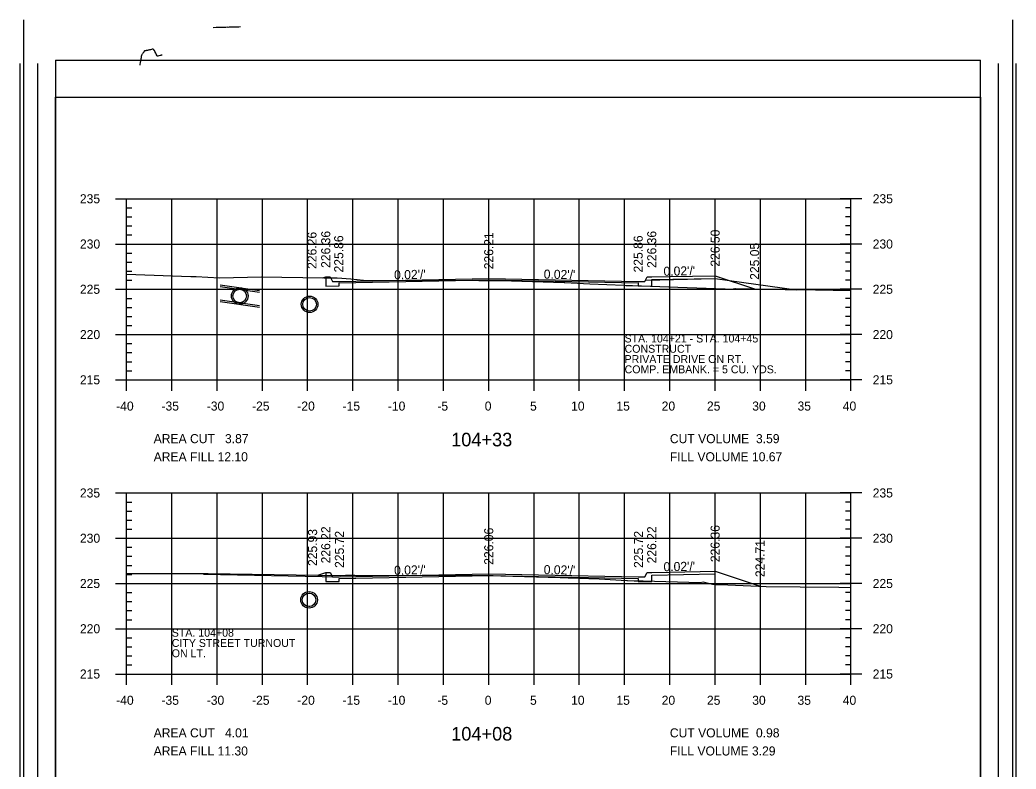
# Model space of a CAD drawing. Extents: x 1367903 to 1373764, y 376865 to 382130.
# Drawn here: x 1370689.3 to 1370909.3, y 377454.8 to 377620.4 of the extents above; entities that cross this region are included whole.
import ezdxf

# ---------------------------------------------------------------- set-up
doc = ezdxf.new("R2010")
doc.units = 0
for name, color, linetype in [('R_Axis', 7, 'Continuous'), ('R_Axis Annot', 7, 'Continuous'), ('R_Border', 7, 'Continuous'), ('R_Border PE', 7, 'Continuous'), ('R_Draft', 7, 'Continuous'), ('R_Drive', 7, 'Continuous'), ('R_Exist Surface', 7, 'Continuous'), ('R_Fin Surface', 7, 'Continuous'), ('R_Fin Surface Annot', 7, 'Continuous'), ('R_Grid', 7, 'Continuous'), ('R_Water', 7, 'Continuous')]:
    doc.layers.add(name, color=color, linetype=linetype)

msp = doc.modelspace()

# ---------------------------------------------------------------- linework, layer by layer
for points in [[(1370756.87, 377563.56), (1370756.87, 377562.89), (1370756.87, 377562.89), (1370756.87, 377561.53), (1370759.87, 377561.59), (1370759.87, 377562.25), (1370792.87, 377562.91), (1370825.87, 377562.25), (1370825.87, 377561.59), (1370828.87, 377561.53), (1370828.87, 377562.97), (1370842.87, 377563.25), (1370842.87, 377563.84)], [(1370756.87, 377498.28), (1370756.87, 377497.61), (1370756.87, 377497.61), (1370756.87, 377496.25), (1370759.87, 377496.31), (1370759.87, 377496.97), (1370792.87, 377497.63), (1370825.87, 377496.97), (1370825.87, 377496.31), (1370828.87, 377496.25), (1370828.87, 377497.69), (1370842.87, 377497.97), (1370842.87, 377498.56)]]:
    msp.add_lwpolyline(points)
at = {"layer": 'R_Axis'}
for p, q in [((1370710.47, 377580.84), (1370715.27, 377580.84)), ((1370712.87, 377540.84), (1370712.87, 377580.84)), ((1370875.27, 377580.84), (1370870.47, 377580.84)), ((1370872.87, 377540.84), (1370872.87, 377580.84)), ((1370712.87, 377578.84), (1370714.07, 377578.84)), ((1370872.87, 377578.84), (1370871.67, 377578.84)), ((1370712.87, 377576.84), (1370714.07, 377576.84)), ((1370872.87, 377576.84), (1370871.67, 377576.84)), ((1370712.87, 377574.84), (1370714.07, 377574.84)), ((1370872.87, 377574.84), (1370871.67, 377574.84)), ((1370712.87, 377572.84), (1370714.07, 377572.84)), ((1370872.87, 377572.84), (1370871.67, 377572.84)), ((1370710.47, 377570.84), (1370715.27, 377570.84)), ((1370875.27, 377570.84), (1370870.47, 377570.84)), ((1370712.87, 377568.84), (1370714.07, 377568.84)), ((1370712.87, 377566.84), (1370714.07, 377566.84)), ((1370872.87, 377568.84), (1370871.67, 377568.84)), ((1370872.87, 377566.84), (1370871.67, 377566.84)), ((1370712.87, 377564.84), (1370714.07, 377564.84)), ((1370872.87, 377564.84), (1370871.67, 377564.84)), ((1370712.87, 377562.84), (1370714.07, 377562.84)), ((1370872.87, 377562.84), (1370871.67, 377562.84)), ((1370710.47, 377560.84), (1370715.27, 377560.84)), ((1370875.27, 377560.84), (1370870.47, 377560.84)), ((1370712.87, 377558.84), (1370714.07, 377558.84)), ((1370872.87, 377558.84), (1370871.67, 377558.84)), ((1370712.87, 377556.84), (1370714.07, 377556.84)), ((1370872.87, 377556.84), (1370871.67, 377556.84)), ((1370712.87, 377554.84), (1370714.07, 377554.84)), ((1370872.87, 377554.84), (1370871.67, 377554.84)), ((1370712.87, 377552.84), (1370714.07, 377552.84)), ((1370872.87, 377552.84), (1370871.67, 377552.84)), ((1370710.47, 377550.84), (1370715.27, 377550.84)), ((1370875.27, 377550.84), (1370870.47, 377550.84)), ((1370712.87, 377548.84), (1370714.07, 377548.84)), ((1370872.87, 377548.84), (1370871.67, 377548.84)), ((1370712.87, 377546.84), (1370714.07, 377546.84)), ((1370712.87, 377544.84), (1370714.07, 377544.84)), ((1370872.87, 377546.84), (1370871.67, 377546.84)), ((1370872.87, 377544.84), (1370871.67, 377544.84)), ((1370712.87, 377538.44), (1370712.87, 377543.24)), ((1370712.87, 377542.84), (1370714.07, 377542.84)), ((1370722.87, 377538.44), (1370722.87, 377543.24)), ((1370732.87, 377538.44), (1370732.87, 377543.24)), ((1370742.87, 377538.44), (1370742.87, 377543.24)), ((1370752.87, 377538.44), (1370752.87, 377543.24)), ((1370762.87, 377538.44), (1370762.87, 377543.24)), ((1370772.87, 377538.44), (1370772.87, 377543.24)), ((1370782.87, 377538.44), (1370782.87, 377543.24)), ((1370792.87, 377538.44), (1370792.87, 377543.24)), ((1370802.87, 377538.44), (1370802.87, 377543.24)), ((1370812.87, 377538.44), (1370812.87, 377543.24)), ((1370822.87, 377538.44), (1370822.87, 377543.24)), ((1370832.87, 377538.44), (1370832.87, 377543.24)), ((1370842.87, 377538.44), (1370842.87, 377543.24)), ((1370852.87, 377538.44), (1370852.87, 377543.24)), ((1370862.87, 377538.44), (1370862.87, 377543.24)), ((1370872.87, 377542.84), (1370871.67, 377542.84)), ((1370872.87, 377538.44), (1370872.87, 377543.24)), ((1370710.47, 377540.84), (1370715.27, 377540.84)), ((1370712.87, 377540.84), (1370872.87, 377540.84)), ((1370875.27, 377540.84), (1370870.47, 377540.84)), ((1370710.47, 377515.84), (1370715.27, 377515.84)), ((1370712.87, 377475.84), (1370712.87, 377515.84)), ((1370875.27, 377515.84), (1370870.47, 377515.84)), ((1370872.87, 377475.84), (1370872.87, 377515.84)), ((1370712.87, 377513.84), (1370714.07, 377513.84)), ((1370712.87, 377511.84), (1370714.07, 377511.84)), ((1370872.87, 377513.84), (1370871.67, 377513.84)), ((1370872.87, 377511.84), (1370871.67, 377511.84)), ((1370712.87, 377509.84), (1370714.07, 377509.84)), ((1370872.87, 377509.84), (1370871.67, 377509.84)), ((1370712.87, 377507.84), (1370714.07, 377507.84)), ((1370872.87, 377507.84), (1370871.67, 377507.84)), ((1370710.47, 377505.84), (1370715.27, 377505.84)), ((1370875.27, 377505.84), (1370870.47, 377505.84)), ((1370712.87, 377503.84), (1370714.07, 377503.84)), ((1370872.87, 377503.84), (1370871.67, 377503.84)), ((1370712.87, 377501.84), (1370714.07, 377501.84)), ((1370872.87, 377501.84), (1370871.67, 377501.84)), ((1370712.87, 377499.84), (1370714.07, 377499.84)), ((1370872.87, 377499.84), (1370871.67, 377499.84)), ((1370712.87, 377497.84), (1370714.07, 377497.84)), ((1370872.87, 377497.84), (1370871.67, 377497.84)), ((1370710.47, 377495.84), (1370715.27, 377495.84)), ((1370875.27, 377495.84), (1370870.47, 377495.84)), ((1370712.87, 377493.84), (1370714.07, 377493.84)), ((1370872.87, 377493.84), (1370871.67, 377493.84)), ((1370712.87, 377491.84), (1370714.07, 377491.84)), ((1370712.87, 377489.84), (1370714.07, 377489.84)), ((1370872.87, 377491.84), (1370871.67, 377491.84)), ((1370872.87, 377489.84), (1370871.67, 377489.84)), ((1370712.87, 377487.84), (1370714.07, 377487.84)), ((1370872.87, 377487.84), (1370871.67, 377487.84)), ((1370710.47, 377485.84), (1370715.27, 377485.84)), ((1370875.27, 377485.84), (1370870.47, 377485.84)), ((1370712.87, 377483.84), (1370714.07, 377483.84)), ((1370872.87, 377483.84), (1370871.67, 377483.84)), ((1370712.87, 377481.84), (1370714.07, 377481.84)), ((1370872.87, 377481.84), (1370871.67, 377481.84)), ((1370712.87, 377479.84), (1370714.07, 377479.84)), ((1370872.87, 377479.84), (1370871.67, 377479.84)), ((1370712.87, 377473.44), (1370712.87, 377478.24)), ((1370712.87, 377477.84), (1370714.07, 377477.84)), ((1370722.87, 377473.44), (1370722.87, 377478.24)), ((1370732.87, 377473.44), (1370732.87, 377478.24)), ((1370742.87, 377473.44), (1370742.87, 377478.24)), ((1370752.87, 377473.44), (1370752.87, 377478.24)), ((1370762.87, 377473.44), (1370762.87, 377478.24)), ((1370772.87, 377473.44), (1370772.87, 377478.24)), ((1370782.87, 377473.44), (1370782.87, 377478.24)), ((1370792.87, 377473.44), (1370792.87, 377478.24)), ((1370802.87, 377473.44), (1370802.87, 377478.24)), ((1370812.87, 377473.44), (1370812.87, 377478.24)), ((1370822.87, 377473.44), (1370822.87, 377478.24)), ((1370832.87, 377473.44), (1370832.87, 377478.24)), ((1370842.87, 377473.44), (1370842.87, 377478.24)), ((1370852.87, 377473.44), (1370852.87, 377478.24)), ((1370862.87, 377473.44), (1370862.87, 377478.24)), ((1370872.87, 377477.84), (1370871.67, 377477.84)), ((1370872.87, 377473.44), (1370872.87, 377478.24)), ((1370710.47, 377475.84), (1370715.27, 377475.84)), ((1370712.87, 377475.84), (1370872.87, 377475.84)), ((1370875.27, 377475.84), (1370870.47, 377475.84))]:
    msp.add_line(p, q, dxfattribs=at)
at = {"layer": 'R_Border'}
for p, q in [((1370690.14, 377620.35), (1370690.14, 377279.12)), ((1370908.53, 377620.35), (1370908.53, 377279.12)), ((1370697.17, 377611.47), (1370901.49, 377611.47)), ((1370697.17, 377611.47), (1370697.17, 377280.59)), ((1370901.49, 377280.59), (1370901.49, 377611.47))]:
    msp.add_line(p, q, dxfattribs=at)
at = {"layer": 'R_Border PE'}
for p, q in [((1370689.33, 377610.76), (1370689.33, 377288.8)), ((1370693.25, 377610.76), (1370693.25, 377288.8)), ((1370905.42, 377288.8), (1370905.42, 377610.76)), ((1370909.33, 377288.8), (1370909.33, 377610.76)), ((1370697.17, 377603.25), (1370901.49, 377603.25)), ((1370697.17, 377288.8), (1370697.17, 377603.25)), ((1370901.49, 377603.25), (1370901.49, 377288.8))]:
    msp.add_line(p, q, dxfattribs=at)
for points in [[(1370734.03, 377618.69), (1370733.97, 377618.69), (1370733.7, 377618.68), (1370733.57, 377618.68), (1370733.49, 377618.67), (1370733.34, 377618.67), (1370732.98, 377618.66), (1370732.65, 377618.65), (1370732.02, 377618.63)], [(1370734.48, 377618.7), (1370734.03, 377618.69)], [(1370738.04, 377618.79), (1370737.69, 377618.78), (1370737.5, 377618.78), (1370737.34, 377618.77), (1370737.11, 377618.76), (1370736.95, 377618.76), (1370736.76, 377618.75), (1370736.51, 377618.75), (1370736.32, 377618.74), (1370736.03, 377618.73), (1370735.94, 377618.73), (1370735.88, 377618.73), (1370735.67, 377618.72), (1370735.56, 377618.72), (1370735.34, 377618.71), (1370735.26, 377618.72), (1370734.84, 377618.7), (1370734.59, 377618.7), (1370734.48, 377618.7)], [(1370720.72, 377612.54), (1370720.71, 377612.55), (1370720.69, 377612.55), (1370720.66, 377612.55), (1370720.64, 377612.55), (1370720.62, 377612.55), (1370720.59, 377612.55), (1370720.56, 377612.55), (1370720.43, 377612.51), (1370720.31, 377612.48), (1370720.04, 377612.41), (1370719.82, 377612.36), (1370719.8, 377612.35), (1370719.77, 377612.35), (1370719.75, 377612.34), (1370719.74, 377612.34), (1370719.73, 377612.35), (1370719.71, 377612.35), (1370719.68, 377612.36), (1370719.66, 377612.38), (1370719.64, 377612.39), (1370719.62, 377612.4), (1370719.6, 377612.42), (1370719.59, 377612.45), (1370719.57, 377612.47), (1370719.56, 377612.5), (1370719.54, 377612.55), (1370719.44, 377612.76), (1370719.33, 377613), (1370719.23, 377613.23), (1370719.21, 377613.26), (1370719.2, 377613.28), (1370719.17, 377613.34), (1370719.13, 377613.39), (1370719.02, 377613.57), (1370718.94, 377613.69), (1370718.91, 377613.74), (1370718.89, 377613.76), (1370718.87, 377613.78), (1370718.85, 377613.81), (1370718.83, 377613.83), (1370718.82, 377613.84), (1370718.8, 377613.85), (1370718.78, 377613.87), (1370718.77, 377613.87), (1370718.73, 377613.88), (1370718.71, 377613.88), (1370718.69, 377613.88), (1370718.66, 377613.88), (1370718.55, 377613.86), (1370718.38, 377613.82), (1370718.18, 377613.77), (1370718.04, 377613.74), (1370717.94, 377613.72), (1370717.8, 377613.69), (1370717.68, 377613.66), (1370717.5, 377613.63), (1370717.28, 377613.58), (1370717.23, 377613.57), (1370717.11, 377613.54), (1370716.99, 377613.52), (1370716.95, 377613.51), (1370716.93, 377613.5), (1370716.9, 377613.5), (1370716.89, 377613.49), (1370716.88, 377613.49), (1370716.86, 377613.47), (1370716.83, 377613.46), (1370716.82, 377613.44), (1370716.79, 377613.42), (1370716.76, 377613.39), (1370716.73, 377613.35), (1370716.71, 377613.31), (1370716.67, 377613.26), (1370716.6, 377613.16), (1370716.51, 377613.02), (1370716.43, 377612.89), (1370716.33, 377612.75), (1370716.29, 377612.67), (1370716.25, 377612.62), (1370716.21, 377612.55), (1370716.2, 377612.54), (1370716.19, 377612.52), (1370716.18, 377612.5), (1370716.18, 377612.48), (1370716.17, 377612.46), (1370716.16, 377612.44), (1370716.16, 377612.42), (1370716.15, 377612.39), (1370716.14, 377612.37), (1370716.14, 377612.35), (1370716.14, 377612.33), (1370716.12, 377612.24), (1370716.08, 377612), (1370716.04, 377611.76), (1370716.02, 377611.65), (1370715.93, 377611.18), (1370715.9, 377611.04), (1370715.87, 377610.84), (1370715.81, 377610.54), (1370715.78, 377610.39)]]:
    msp.add_lwpolyline(points, dxfattribs=at)
at = {"layer": 'R_Drive'}
for p, q in [((1370827.53, 377562.89), (1370842.86, 377563.19)), ((1370842.86, 377563.19), (1370860.87, 377560.75)), ((1370729.87, 377497.9), (1370712.87, 377497.99)), ((1370729.87, 377497.9), (1370759.87, 377497.31))]:
    msp.add_line(p, q, dxfattribs=at)
at = {"layer": 'R_Exist Surface'}
for points in [[(1370712.87, 377564.2), (1370727.11, 377563.68), (1370728.26, 377563.65), (1370733.43, 377563.35), (1370742.68, 377563.56), (1370747.14, 377563.51), (1370756.46, 377563.35), (1370759.41, 377563.38), (1370762.41, 377563.17), (1370765.18, 377562.85), (1370790.66, 377562.81), (1370793.77, 377562.8), (1370795.54, 377562.75), (1370809.5, 377562.35), (1370809.71, 377562.35), (1370811.04, 377562.29), (1370815.18, 377562.08), (1370822.72, 377561.74), (1370823.18, 377561.7), (1370824.59, 377561.71), (1370834.64, 377561.33), (1370845.05, 377560.91), (1370846.42, 377560.87), (1370847.23, 377561.01), (1370847.37, 377561.02), (1370858.36, 377560.78), (1370865.02, 377560.69), (1370872.87, 377560.55)], [(1370712.87, 377498.02), (1370730.79, 377498.06), (1370730.86, 377498.06), (1370730.9, 377498.06), (1370760.03, 377497.63), (1370761.21, 377497.65), (1370763.2, 377497.7), (1370763.29, 377497.71), (1370791.93, 377497.6), (1370793.86, 377497.59), (1370795.54, 377497.55), (1370800.8, 377497.4), (1370808.63, 377497.19), (1370810.4, 377497.12), (1370817.29, 377496.9), (1370823.4, 377496.5), (1370823.54, 377496.5), (1370825.02, 377496.45), (1370826.99, 377496.4), (1370839.55, 377496.04), (1370840.2, 377496.24), (1370842.26, 377495.7), (1370842.86, 377495.65), (1370845.69, 377495.51), (1370852.44, 377495.27), (1370854.14, 377495.2), (1370861.63, 377495.08), (1370870.19, 377495), (1370872.87, 377494.98)]]:
    msp.add_lwpolyline(points, dxfattribs=at)
at = {"layer": 'R_Fin Surface'}
for points in [[(1370756.24, 377563.35), (1370756.87, 377563.56), (1370757.87, 377563.56), (1370758.37, 377562.56), (1370759.87, 377562.59), (1370781.87, 377563.03), (1370792.87, 377563.25), (1370803.87, 377563.03), (1370825.87, 377562.59), (1370827.37, 377562.56), (1370827.87, 377563.56), (1370828.87, 377563.56), (1370832.87, 377563.64), (1370842.87, 377563.84), (1370851.59, 377560.93)], [(1370755.15, 377497.7), (1370756.87, 377498.28), (1370757.87, 377498.28), (1370758.37, 377497.28), (1370759.87, 377497.31), (1370781.87, 377497.75), (1370792.87, 377497.97), (1370803.87, 377497.75), (1370825.87, 377497.31), (1370827.37, 377497.28), (1370827.87, 377498.28), (1370828.87, 377498.28), (1370832.87, 377498.36), (1370842.87, 377498.56), (1370852.78, 377495.25)]]:
    msp.add_lwpolyline(points, dxfattribs=at)
at = {"layer": 'R_Grid'}
for p, q in [((1370712.87, 377580.84), (1370872.87, 377580.84)), ((1370712.87, 377540.84), (1370712.87, 377580.84)), ((1370722.87, 377540.84), (1370722.87, 377580.84)), ((1370732.87, 377540.84), (1370732.87, 377580.84)), ((1370742.87, 377540.84), (1370742.87, 377580.84)), ((1370752.87, 377540.84), (1370752.87, 377580.84)), ((1370762.87, 377540.84), (1370762.87, 377580.84)), ((1370772.87, 377540.84), (1370772.87, 377580.84)), ((1370782.87, 377540.84), (1370782.87, 377580.84)), ((1370792.87, 377540.84), (1370792.87, 377580.84)), ((1370802.87, 377540.84), (1370802.87, 377580.84)), ((1370812.87, 377540.84), (1370812.87, 377580.84)), ((1370822.87, 377540.84), (1370822.87, 377580.84)), ((1370832.87, 377540.84), (1370832.87, 377580.84)), ((1370842.87, 377540.84), (1370842.87, 377580.84)), ((1370852.87, 377540.84), (1370852.87, 377580.84)), ((1370862.87, 377540.84), (1370862.87, 377580.84)), ((1370872.87, 377540.84), (1370872.87, 377580.84)), ((1370712.87, 377570.84), (1370872.87, 377570.84)), ((1370712.87, 377560.84), (1370872.87, 377560.84)), ((1370712.87, 377550.84), (1370872.87, 377550.84)), ((1370712.87, 377540.84), (1370872.87, 377540.84)), ((1370712.87, 377515.84), (1370872.87, 377515.84)), ((1370712.87, 377475.84), (1370712.87, 377515.84)), ((1370722.87, 377475.84), (1370722.87, 377515.84)), ((1370732.87, 377475.84), (1370732.87, 377515.84)), ((1370742.87, 377475.84), (1370742.87, 377515.84)), ((1370752.87, 377475.84), (1370752.87, 377515.84)), ((1370762.87, 377475.84), (1370762.87, 377515.84)), ((1370772.87, 377475.84), (1370772.87, 377515.84)), ((1370782.87, 377475.84), (1370782.87, 377515.84)), ((1370792.87, 377475.84), (1370792.87, 377515.84)), ((1370802.87, 377475.84), (1370802.87, 377515.84)), ((1370812.87, 377475.84), (1370812.87, 377515.84)), ((1370822.87, 377475.84), (1370822.87, 377515.84)), ((1370832.87, 377475.84), (1370832.87, 377515.84)), ((1370842.87, 377475.84), (1370842.87, 377515.84)), ((1370852.87, 377475.84), (1370852.87, 377515.84)), ((1370862.87, 377475.84), (1370862.87, 377515.84)), ((1370872.87, 377475.84), (1370872.87, 377515.84)), ((1370712.87, 377505.84), (1370872.87, 377505.84)), ((1370712.87, 377495.84), (1370872.87, 377495.84)), ((1370712.87, 377485.84), (1370872.87, 377485.84)), ((1370712.87, 377475.84), (1370872.87, 377475.84))]:
    msp.add_line(p, q, dxfattribs=at)
at = {"layer": 'R_Water'}
for p, q in [((1370733.53, 377561.81), (1370742.24, 377560.57)), ((1370733.53, 377561.48), (1370742.24, 377560.24)), ((1370733.53, 377558.48), (1370742.24, 377557.24)), ((1370733.53, 377558.14), (1370742.24, 377556.9)), ((1370753.32, 377559.38), (1370753.28, 377559.33)), ((1370753.32, 377559.05), (1370753.28, 377559)), ((1370753.32, 377556.05), (1370753.28, 377556)), ((1370753.32, 377555.71), (1370753.28, 377555.67)), ((1370753.19, 377494.09), (1370753.19, 377494.04)), ((1370753.19, 377493.75), (1370753.19, 377493.71)), ((1370753.19, 377490.75), (1370753.19, 377490.71)), ((1370753.19, 377490.42), (1370753.19, 377490.37))]:
    msp.add_line(p, q, dxfattribs=at)
for centre, radius in [((1370737.88, 377559.36), 1.83), ((1370737.88, 377559.36), 1.5), ((1370753.3, 377557.52), 1.83), ((1370753.3, 377557.52), 1.5), ((1370753.19, 377492.23), 1.83), ((1370753.19, 377492.23), 1.5)]:
    msp.add_circle(centre, radius, dxfattribs=at)

# ---------------------------------------------------------------- texts
at = {"layer": 'R_Axis Annot'}
for s, height, p in [('235', 2, (1370702.58, 377579.84)), ('235', 2, (1370877.67, 377579.84)), ('230', 2, (1370702.59, 377569.84)), ('230', 2, (1370877.67, 377569.84)), ('225', 2, (1370702.58, 377559.84)), ('225', 2, (1370877.67, 377559.84)), ('220', 2, (1370702.59, 377549.84)), ('220', 2, (1370877.67, 377549.84)), ('215', 2, (1370702.58, 377539.84)), ('215', 2, (1370877.67, 377539.84)), ('-40', 2, (1370710.59, 377534.04)), ('-35', 2, (1370720.59, 377534.04)), ('-30', 2, (1370730.59, 377534.04)), ('-25', 2, (1370740.59, 377534.04)), ('-20', 2, (1370750.59, 377534.04)), ('-15', 2, (1370760.59, 377534.04)), ('-10', 2, (1370770.59, 377534.04)), ('-5', 2, (1370781.52, 377534.04)), ('0', 2, (1370791.99, 377534.04)), ('5', 2, (1370801.99, 377534.04)), ('10', 2, (1370811.06, 377534.04)), ('15', 2, (1370821.06, 377534.04)), ('20', 2, (1370831.06, 377534.04)), ('25', 2, (1370841.06, 377534.04)), ('30', 2, (1370851.06, 377534.04)), ('35', 2, (1370861.06, 377534.04)), ('40', 2, (1370871.06, 377534.04)), ('AREA CUT   3.87', 2, (1370718.87, 377526.84)), ('104+33', 3, (1370784.57, 377526.14)), ('CUT VOLUME  3.59', 2, (1370832.87, 377526.84)), ('AREA FILL 12.10', 2, (1370718.87, 377522.84)), ('FILL VOLUME 10.67', 2, (1370832.87, 377522.84)), ('235', 2, (1370702.58, 377514.84)), ('235', 2, (1370877.67, 377514.84)), ('230', 2, (1370702.59, 377504.84)), ('230', 2, (1370877.67, 377504.84)), ('225', 2, (1370702.58, 377494.84)), ('225', 2, (1370877.67, 377494.84)), ('220', 2, (1370702.59, 377484.84)), ('220', 2, (1370877.67, 377484.84)), ('215', 2, (1370702.58, 377474.84)), ('215', 2, (1370877.67, 377474.84)), ('-40', 2, (1370710.59, 377469.04)), ('-35', 2, (1370720.59, 377469.04)), ('-30', 2, (1370730.59, 377469.04)), ('-25', 2, (1370740.59, 377469.04)), ('-20', 2, (1370750.59, 377469.04)), ('-15', 2, (1370760.59, 377469.04)), ('-10', 2, (1370770.59, 377469.04)), ('-5', 2, (1370781.52, 377469.04)), ('0', 2, (1370791.99, 377469.04)), ('5', 2, (1370801.99, 377469.04)), ('10', 2, (1370811.06, 377469.04)), ('15', 2, (1370821.06, 377469.04)), ('20', 2, (1370831.06, 377469.04)), ('25', 2, (1370841.06, 377469.04)), ('30', 2, (1370851.06, 377469.04)), ('35', 2, (1370861.06, 377469.04)), ('40', 2, (1370871.06, 377469.04)), ('AREA CUT   4.01', 2, (1370718.87, 377461.84)), ('104+08', 3, (1370784.58, 377461.14)), ('CUT VOLUME  0.98', 2, (1370832.87, 377461.84)), ('AREA FILL 11.30', 2, (1370718.87, 377457.84)), ('FILL VOLUME 3.29', 2, (1370832.87, 377457.84))]:
    msp.add_text(s, height=height, dxfattribs=at).set_placement(p)
at = {"layer": 'R_Draft'}
for s, p in [('STA. 104+21 - STA. 104+45', (1370822.87, 377549.09)), ('CONSTRUCT', (1370822.87, 377546.82)), ('PRIVATE DRIVE ON RT.', (1370822.87, 377544.55)), ('COMP. EMBANK. = 5 CU. YDS.', (1370822.87, 377542.28)), ('STA. 104+08', (1370722.87, 377484.09)), ('CITY STREET TURNOUT', (1370722.87, 377481.82)), ('ON LT.', (1370722.87, 377479.55))]:
    msp.add_text(s, height=1.75, dxfattribs=at).set_placement(p)
at = {"layer": 'R_Fin Surface Annot'}
for s, rotation, p in [('226.26', 90, (1370754.83, 377565.35)), ('226.36', 90, (1370757.87, 377565.56)), ('226.36', 90, (1370829.87, 377565.56)), ('226.50', 90, (1370843.87, 377565.84)), ('225.86', 90, (1370760.74, 377564.56)), ('226.21', 90, (1370793.87, 377565.25)), ('225.86', 90, (1370826.87, 377564.56)), ('225.05', 90, (1370852.59, 377562.93)), ("0.02'/'", 1.1458, (1370771.99, 377563.03)), ("0.02'/'", 358.8542, (1370805, 377563.2)), ("0.02'/'", 1.1458, (1370831.49, 377563.81)), ('225.93', 90, (1370754.97, 377499.7)), ('226.22', 90, (1370757.87, 377500.28)), ('226.06', 90, (1370793.87, 377499.97)), ('226.22', 90, (1370829.87, 377500.28)), ('226.36', 90, (1370843.87, 377500.56)), ('225.72', 90, (1370760.89, 377499.28)), ('225.72', 90, (1370826.94, 377499.28)), ('224.71', 90, (1370853.78, 377497.25)), ("0.02'/'", 1.1458, (1370831.49, 377498.53)), ("0.02'/'", 1.1458, (1370771.99, 377497.75)), ("0.02'/'", 358.8542, (1370805, 377497.92))]:
    msp.add_text(s, height=2, rotation=rotation, dxfattribs=at).set_placement(p)

doc.saveas('drawing.dxf')
